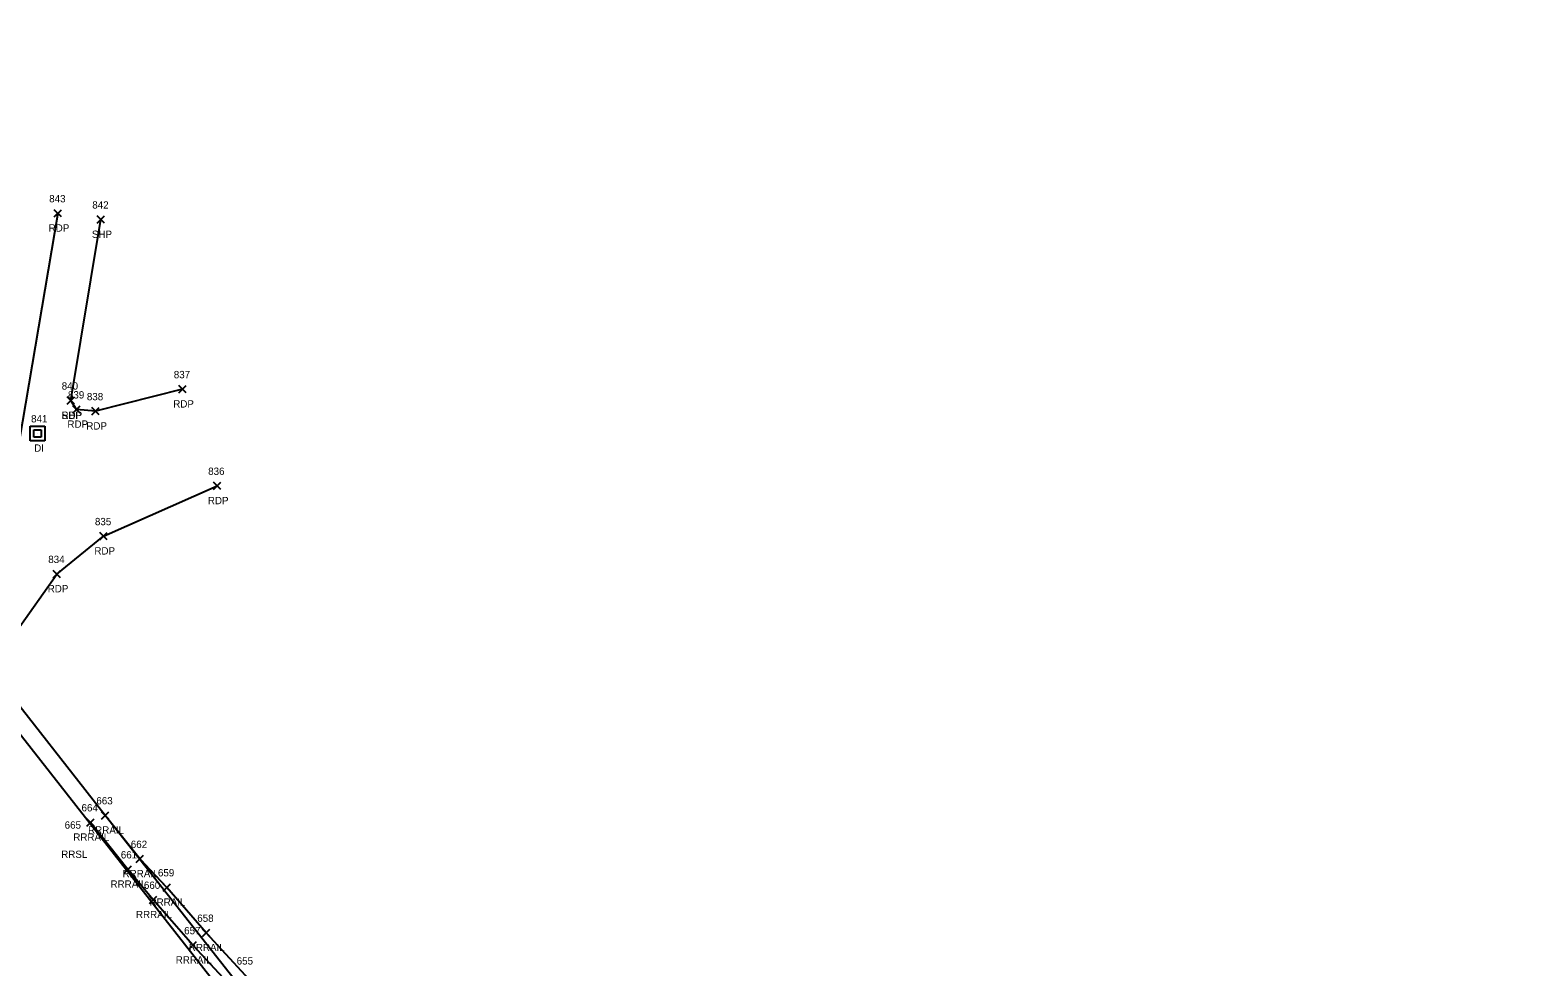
# Model space of a CAD drawing. Extents: x 1615599 to 1619911, y 273782 to 280437.
# Drawn here: x 1616569.8 to 1616981.6, y 279745.5 to 280001.3 of the extents above; entities that cross this region are included whole.
import ezdxf

# ---------------------------------------------------------------- set-up
doc = ezdxf.new("R2010")
doc.units = 0
for name, color, linetype in [('D_A', 7, 'Continuous'), ('D_I', 7, 'Continuous'), ('DS', 7, 'Continuous'), ('P_A', 7, 'Continuous'), ('P_I', 7, 'Continuous'), ('P_TIC', 7, 'Continuous'), ('PET', 7, 'Continuous'), ('PSP', 7, 'Continuous'), ('R_A', 7, 'Continuous'), ('R_I', 7, 'Continuous'), ('R_TIC', 7, 'Continuous'), ('RR', 7, 'Continuous')]:
    doc.layers.add(name, color=color, linetype=linetype)

msp = doc.modelspace()

# ---------------------------------------------------------------- linework, layer by layer
at = {"layer": 'DS'}
for p, q in [((1616569.87, 279893.15), (1616573.87, 279893.15)), ((1616569.87, 279889.15), (1616569.87, 279893.15)), ((1616570.87, 279890.15), (1616570.87, 279892.15)), ((1616570.87, 279892.15), (1616572.87, 279892.15)), ((1616572.87, 279890.15), (1616570.87, 279890.15)), ((1616571.88, 279891.15), (1616571.88, 279891.15)), ((1616571.88, 279891.15), (1616571.88, 279891.15)), ((1616572.87, 279892.15), (1616572.87, 279890.15)), ((1616573.87, 279893.15), (1616573.87, 279889.15)), ((1616573.87, 279889.15), (1616569.87, 279889.15))]:
    msp.add_line(p, q, dxfattribs=at)
at = {"layer": 'P_TIC'}
for points in [[(1616576.39, 279950.25), (1616578.39, 279952.25)], [(1616578.39, 279950.25), (1616576.39, 279952.25)], [(1616588.17, 279948.54), (1616590.17, 279950.54)], [(1616590.17, 279948.54), (1616588.17, 279950.54)], [(1616610.42, 279902.22), (1616612.42, 279904.22)], [(1616612.42, 279902.22), (1616610.42, 279904.22)], [(1616579.9, 279899.11), (1616581.9, 279901.11)], [(1616581.9, 279899.11), (1616579.9, 279901.11)], [(1616579.9, 279899.11), (1616581.9, 279901.11)], [(1616581.9, 279899.11), (1616579.9, 279901.11)], [(1616581.52, 279896.69), (1616583.52, 279898.69)], [(1616583.52, 279896.69), (1616581.52, 279898.69)], [(1616586.68, 279896.2), (1616588.68, 279898.2)], [(1616588.68, 279896.2), (1616586.68, 279898.2)], [(1616619.87, 279875.82), (1616621.87, 279877.82)], [(1616621.87, 279875.82), (1616619.87, 279877.82)], [(1616588.88, 279862.08), (1616590.88, 279864.08)], [(1616590.88, 279862.08), (1616588.88, 279864.08)], [(1616576.14, 279851.75), (1616578.14, 279853.75)], [(1616578.14, 279851.75), (1616576.14, 279853.75)]]:
    msp.add_lwpolyline(points, dxfattribs=at)
at = {"layer": 'PET'}
for points in [[(1616577.39, 279951.25), (1616566.79, 279889.02), (1616558.96, 279848.34)], [(1616611.42, 279903.22), (1616587.68, 279897.2), (1616582.52, 279897.69), (1616580.9, 279900.11)], [(1616526.87, 279479.75), (1616534.9, 279608.29), (1616540.12, 279681.26), (1616545.34, 279739.77), (1616548.4, 279773.98), (1616552.49, 279810.18), (1616554.63, 279819.12), (1616562.79, 279830.13), (1616562.2, 279831.59), (1616577.14, 279852.75), (1616589.88, 279863.08), (1616620.87, 279876.82)]]:
    msp.add_lwpolyline(points, dxfattribs=at)
at = {"layer": 'PSP'}
msp.add_lwpolyline([(1616580.9, 279900.11), (1616589.17, 279949.54)], dxfattribs=at)
at = {"layer": 'R_TIC'}
for points in [[(1616589.36, 279785.85), (1616591.36, 279787.85)], [(1616591.36, 279785.85), (1616589.36, 279787.85)], [(1616589.36, 279785.85), (1616591.36, 279787.85)], [(1616591.36, 279785.85), (1616589.36, 279787.85)], [(1616585.32, 279783.93), (1616587.32, 279785.93)], [(1616587.32, 279783.93), (1616585.32, 279785.93)], [(1616598.77, 279773.94), (1616600.77, 279775.94)], [(1616600.77, 279773.94), (1616598.77, 279775.94)], [(1616595.48, 279771.09), (1616597.48, 279773.09)], [(1616597.48, 279771.09), (1616595.48, 279773.09)], [(1616606.15, 279766.18), (1616608.15, 279768.18)], [(1616608.15, 279766.18), (1616606.15, 279768.18)], [(1616602.44, 279762.78), (1616604.44, 279764.78)], [(1616604.44, 279762.78), (1616602.44, 279764.78)], [(1616616.88, 279753.77), (1616618.88, 279755.77)], [(1616618.88, 279753.77), (1616616.88, 279755.77)], [(1616613.3, 279750.39), (1616615.3, 279752.39)], [(1616615.3, 279750.39), (1616613.3, 279752.39)]]:
    msp.add_lwpolyline(points, dxfattribs=at)
at = {"layer": 'RR'}
for points in [[(1618859.75, 276891.53), (1618799.24, 276968.15), (1618284.94, 277623.12), (1618268.81, 277643.64), (1617626.81, 278460.24), (1617616.13, 278473.64), (1617546.95, 278561.72), (1617499.49, 278621.79), (1617406.55, 278740.52), (1617357.63, 278802.9), (1617271.97, 278912.55), (1616838.51, 279463.88), (1616791.25, 279524.04), (1616711.4, 279625.23), (1616195.43, 280281.84), (1616147.06, 280342.91)], [(1618863.67, 276894.43), (1618803.13, 276971.25), (1618287.89, 277627.49), (1618272.16, 277647.46), (1617630.42, 278463.6), (1617620.37, 278476.22), (1617582.75, 278523.92), (1617266.97, 278926.89), (1616715.35, 279628.09), (1616637.52, 279726.94), (1616590.36, 279786.85), (1616151.06, 280346.19)], [(1617630.42, 278463.6), (1617620.82, 278476.43), (1617606.54, 278496.62), (1617593.5, 278516.12), (1617586.3, 278527.38), (1617567.87, 278556.66), (1617553.59, 278578.19), (1617540.33, 278596.98), (1617518.68, 278626.03), (1617484.75, 278670.09), (1617274.79, 278937.46), (1616726.46, 279635.17), (1616720, 279643.16), (1616701.68, 279664.74), (1616684.77, 279683.78), (1616667.83, 279702.27), (1616651.55, 279719.29), (1616640.89, 279730.27), (1616628.65, 279743.11), (1616617.88, 279754.77), (1616607.15, 279767.18), (1616599.77, 279774.94), (1616590.36, 279786.85)], [(1617627.18, 278460.59), (1617616.67, 278473.78), (1617602.72, 278493.41), (1617589.08, 278513.87), (1617582.75, 278523.92), (1617563.26, 278554.55), (1617549.48, 278575.26), (1617536.29, 278594.04), (1617514.68, 278623.03), (1617480.83, 278667.07), (1617271.03, 278934.24), (1616722.48, 279632.31), (1616715.66, 279640.54), (1616698.06, 279661.21), (1616680.81, 279680.73), (1616664.6, 279698.33), (1616647.93, 279715.86), (1616637.52, 279726.94), (1616624.98, 279739.87), (1616614.3, 279751.39), (1616603.44, 279763.78), (1616596.48, 279772.09), (1616586.32, 279784.93)]]:
    msp.add_lwpolyline(points, dxfattribs=at)

# ---------------------------------------------------------------- texts
at = {"layer": 'D_A'}
msp.add_text('DI', height=2, dxfattribs=at).set_placement((1616570.93, 279886.15))
at = {"layer": 'D_I'}
msp.add_text('841', height=2, dxfattribs=at).set_placement((1616570.08, 279894.15))
at = {"layer": 'P_A'}
for s, p in [('RDP', (1616574.88, 279946.25)), ('SHP', (1616586.7, 279944.54)), ('RDP', (1616608.91, 279898.22)), ('SHP', (1616578.44, 279895.11)), ('RDP', (1616578.39, 279895.11)), ('RDP', (1616580.01, 279892.69)), ('RDP', (1616585.17, 279892.2)), ('RDP', (1616618.36, 279871.82)), ('RDP', (1616587.37, 279858.08)), ('RDP', (1616574.62, 279847.75))]:
    msp.add_text(s, height=2, dxfattribs=at).set_placement(p)
at = {"layer": 'P_I'}
for s, p in [('843', (1616575.03, 279954.25)), ('842', (1616586.8, 279952.54)), ('837', (1616609.06, 279906.22)), ('840', (1616578.45, 279903.11)), ('840', (1616578.45, 279903.11)), ('839', (1616580.15, 279900.69)), ('838', (1616585.32, 279900.2)), ('836', (1616618.45, 279879.82)), ('835', (1616587.52, 279866.08)), ('834', (1616574.77, 279855.75))]:
    msp.add_text(s, height=2, dxfattribs=at).set_placement(p)
at = {"layer": 'R_A'}
for s, p in [('RRRAIL', (1616585.65, 279781.85)), ('RRRAIL', (1616585.65, 279781.85)), ('RRRAIL', (1616581.61, 279779.93)), ('RRSL', (1616578.31, 279775.22)), ('RRRAIL', (1616595.07, 279769.94)), ('RRRAIL', (1616591.77, 279767.09)), ('RRRAIL', (1616602.44, 279762.18)), ('RRRAIL', (1616598.73, 279758.78)), ('RRRAIL', (1616613.17, 279749.77)), ('RRRAIL', (1616609.59, 279746.39))]:
    msp.add_text(s, height=2, dxfattribs=at).set_placement(p)
at = {"layer": 'R_I'}
for s, p in [('663', (1616587.91, 279789.85)), ('663', (1616587.91, 279789.85)), ('664', (1616583.86, 279787.93)), ('665', (1616579.25, 279783.22)), ('662', (1616597.32, 279777.94)), ('661', (1616594.59, 279775.09)), ('659', (1616604.73, 279770.18)), ('660', (1616600.9, 279766.78)), ('658', (1616615.47, 279757.77)), ('657', (1616611.89, 279754.39)), ('655', (1616626.24, 279746.11))]:
    msp.add_text(s, height=2, dxfattribs=at).set_placement(p)

doc.saveas('drawing.dxf')
